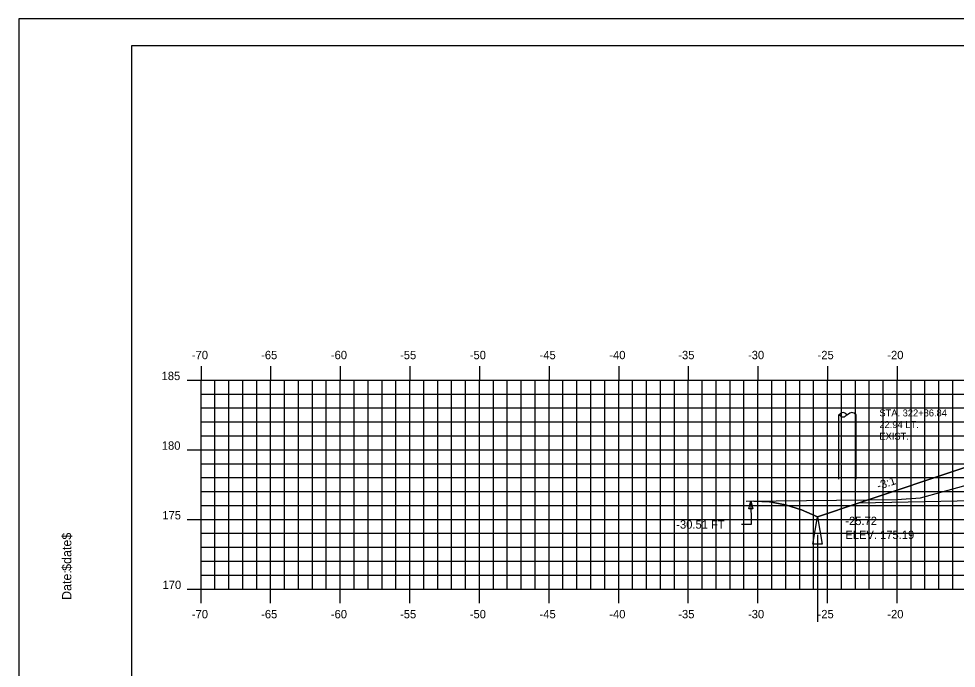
# Model space of a CAD drawing. Extents: x 1140094 to 1140264, y 608981 to 609091.
# Drawn here: x 1140093.6 to 1140161, y 609044.6 to 609091.3 of the extents above; entities that cross this region are included whole.
import ezdxf

# ---------------------------------------------------------------- set-up
doc = ezdxf.new("R2010")
doc.units = 0
for name, color, linetype in [('ANNOTATION', 7, 'Continuous'), ('BORDER', 7, 'Continuous'), ('D_Drainage_Ditch_Line', 7, 'Continuous'), ('D_Roadway_SlopeLines', 7, 'Continuous'), ('D_Roadway_SubGrade', 7, 'Continuous'), ('D_Text_Monospaced', 7, 'Continuous'), ('D_Text_Standard', 7, 'Continuous'), ('H_V ANNOTATION', 7, 'Continuous'), ('MAJOR', 7, 'Continuous'), ('MINOR', 7, 'Continuous'), ('PLOT BOUNDARY', 7, 'Continuous'), ('S_Roadway_Centerline', 7, 'Continuous'), ('S_Utilities_Pole_Power', 7, 'Continuous')]:
    doc.layers.add(name, color=color, linetype=linetype)

msp = doc.modelspace()

# ---------------------------------------------------------------- linework, layer by layer
msp.add_lwpolyline([(1140146.431, 609056.645), (1140147.575, 609056.586), (1140148.719, 609056.38), (1140149.863, 609056.028), (1140151.007, 609055.529), (1140154.007, 609056.529), (1140161.73, 609059.104), (1140161.731, 609059.104), (1140165.731, 609059.264), (1140176.731, 609059.484), (1140187.731, 609059.264), (1140191.731, 609059.104), (1140199.455, 609056.529), (1140202.455, 609055.529), (1140205.798, 609057.201), (1140207.048, 609057.751), (1140208.298, 609058.153), (1140209.548, 609058.405), (1140210.798, 609058.508)])
at = {"layer": 'BORDER'}
msp.add_lwpolyline([(1140101.732, 608984.335), (1140261.732, 608984.335), (1140261.732, 609089.335), (1140101.732, 609089.335)], close=True, dxfattribs=at)
at = {"layer": 'D_Drainage_Ditch_Line'}
msp.add_line((1140151.007, 609054.217), (1140151.006, 609047.974), dxfattribs=at)
msp.add_lwpolyline([(1140151.335, 609053.561), (1140150.679, 609053.561), (1140151.007, 609055.529)], close=True, dxfattribs=at)
at = {"layer": 'D_Roadway_SlopeLines'}
for points in [[(1140151.007, 609055.529), (1140149.863, 609056.028), (1140148.719, 609056.38), (1140147.575, 609056.586), (1140146.431, 609056.645)], [(1140154.007, 609056.529), (1140151.007, 609055.529)]]:
    msp.add_lwpolyline(points, dxfattribs=at)
at = {"layer": 'D_Roadway_SubGrade'}
msp.add_lwpolyline([(1140165.731, 609058.847), (1140165.731, 609059.014), (1140161.731, 609058.854), (1140161.731, 609059.104), (1140161.73, 609059.104), (1140154.007, 609056.529), (1140165.731, 609056.764)], close=True, dxfattribs=at)
at = {"layer": 'D_Text_Standard'}
msp.add_lwpolyline([(1140146.219, 609056.673), (1140146.241, 609054.971), (1140145.561, 609054.971)], dxfattribs=at)
msp.add_lwpolyline([(1140146.219, 609056.673), (1140146.372, 609056.093), (1140146.081, 609056.089)], close=True, dxfattribs=at)
at = {"layer": 'MAJOR'}
for p, q in [((1140106.731, 609066.337), (1140106.731, 609065.335)), ((1140111.731, 609066.337), (1140111.731, 609065.335)), ((1140116.731, 609066.337), (1140116.731, 609065.335)), ((1140121.731, 609066.337), (1140121.731, 609065.335)), ((1140126.731, 609066.337), (1140126.731, 609065.335)), ((1140131.731, 609066.337), (1140131.731, 609065.335)), ((1140136.731, 609066.337), (1140136.731, 609065.335)), ((1140141.731, 609066.337), (1140141.731, 609065.335)), ((1140146.731, 609066.337), (1140146.731, 609065.335)), ((1140151.731, 609066.337), (1140151.731, 609065.335)), ((1140156.731, 609066.337), (1140156.731, 609065.335)), ((1140105.729, 609065.335), (1140106.731, 609065.335)), ((1140106.731, 609065.335), (1140246.731, 609065.335)), ((1140106.731, 609050.335), (1140106.731, 609065.335)), ((1140106.731, 609050.335), (1140106.731, 609065.335)), ((1140106.731, 609065.335), (1140246.731, 609065.335)), ((1140111.731, 609050.335), (1140111.731, 609065.335)), ((1140116.731, 609050.335), (1140116.731, 609065.335)), ((1140121.731, 609050.335), (1140121.731, 609065.335)), ((1140126.731, 609050.335), (1140126.731, 609065.335)), ((1140131.731, 609050.335), (1140131.731, 609065.335)), ((1140136.731, 609050.335), (1140136.731, 609065.335)), ((1140141.731, 609050.335), (1140141.731, 609065.335)), ((1140146.731, 609050.335), (1140146.731, 609065.335)), ((1140151.731, 609050.335), (1140151.731, 609065.335)), ((1140156.731, 609050.335), (1140156.731, 609065.335)), ((1140105.729, 609060.335), (1140106.731, 609060.335)), ((1140106.731, 609060.335), (1140246.731, 609060.335)), ((1140105.729, 609055.335), (1140106.731, 609055.335)), ((1140106.731, 609055.335), (1140246.731, 609055.335)), ((1140105.729, 609050.335), (1140106.731, 609050.335)), ((1140106.731, 609050.335), (1140246.731, 609050.335)), ((1140106.731, 609050.335), (1140246.731, 609050.335)), ((1140106.731, 609049.333), (1140106.731, 609050.335)), ((1140111.731, 609049.333), (1140111.731, 609050.335)), ((1140116.731, 609049.333), (1140116.731, 609050.335)), ((1140121.731, 609049.333), (1140121.731, 609050.335)), ((1140126.731, 609049.333), (1140126.731, 609050.335)), ((1140131.731, 609049.333), (1140131.731, 609050.335)), ((1140136.731, 609049.333), (1140136.731, 609050.335)), ((1140141.731, 609049.333), (1140141.731, 609050.335)), ((1140146.731, 609049.333), (1140146.731, 609050.335)), ((1140151.731, 609049.333), (1140151.731, 609050.335)), ((1140156.731, 609049.333), (1140156.731, 609050.335))]:
    msp.add_line(p, q, dxfattribs=at)
at = {"layer": 'MINOR'}
for p, q in [((1140107.731, 609050.335), (1140107.731, 609065.335)), ((1140108.731, 609050.335), (1140108.731, 609065.335)), ((1140109.731, 609050.335), (1140109.731, 609065.335)), ((1140110.731, 609050.335), (1140110.731, 609065.335)), ((1140112.731, 609050.335), (1140112.731, 609065.335)), ((1140113.731, 609050.335), (1140113.731, 609065.335)), ((1140114.731, 609050.335), (1140114.731, 609065.335)), ((1140115.731, 609050.335), (1140115.731, 609065.335)), ((1140117.731, 609050.335), (1140117.731, 609065.335)), ((1140118.731, 609050.335), (1140118.731, 609065.335)), ((1140119.731, 609050.335), (1140119.731, 609065.335)), ((1140120.731, 609050.335), (1140120.731, 609065.335)), ((1140122.731, 609050.335), (1140122.731, 609065.335)), ((1140123.731, 609050.335), (1140123.731, 609065.335)), ((1140124.731, 609050.335), (1140124.731, 609065.335)), ((1140125.731, 609050.335), (1140125.731, 609065.335)), ((1140127.731, 609050.335), (1140127.731, 609065.335)), ((1140128.731, 609050.335), (1140128.731, 609065.335)), ((1140129.731, 609050.335), (1140129.731, 609065.335)), ((1140130.731, 609050.335), (1140130.731, 609065.335)), ((1140132.731, 609050.335), (1140132.731, 609065.335)), ((1140133.731, 609050.335), (1140133.731, 609065.335)), ((1140134.731, 609050.335), (1140134.731, 609065.335)), ((1140135.731, 609050.335), (1140135.731, 609065.335)), ((1140137.731, 609050.335), (1140137.731, 609065.335)), ((1140138.731, 609050.335), (1140138.731, 609065.335)), ((1140139.731, 609050.335), (1140139.731, 609065.335)), ((1140140.731, 609050.335), (1140140.731, 609065.335)), ((1140142.731, 609050.335), (1140142.731, 609065.335)), ((1140143.731, 609050.335), (1140143.731, 609065.335)), ((1140144.731, 609050.335), (1140144.731, 609065.335)), ((1140145.731, 609050.335), (1140145.731, 609065.335)), ((1140147.731, 609050.335), (1140147.731, 609065.335)), ((1140148.731, 609050.335), (1140148.731, 609065.335)), ((1140149.731, 609050.335), (1140149.731, 609065.335)), ((1140150.731, 609050.335), (1140150.731, 609065.335)), ((1140152.731, 609050.335), (1140152.731, 609065.335)), ((1140153.731, 609050.335), (1140153.731, 609065.335)), ((1140154.731, 609050.335), (1140154.731, 609065.335)), ((1140155.731, 609050.335), (1140155.731, 609065.335)), ((1140157.731, 609050.335), (1140157.731, 609065.335)), ((1140158.731, 609050.335), (1140158.731, 609065.335)), ((1140159.731, 609050.335), (1140159.731, 609065.335)), ((1140160.731, 609050.335), (1140160.731, 609065.335)), ((1140106.731, 609064.335), (1140246.731, 609064.335)), ((1140106.731, 609064.335), (1140107.733, 609064.335)), ((1140106.731, 609063.335), (1140246.731, 609063.335)), ((1140106.731, 609063.335), (1140107.733, 609063.335)), ((1140106.731, 609062.335), (1140246.731, 609062.335)), ((1140106.731, 609062.335), (1140107.733, 609062.335)), ((1140106.731, 609061.335), (1140246.731, 609061.335)), ((1140106.731, 609061.335), (1140107.733, 609061.335)), ((1140106.731, 609059.335), (1140246.731, 609059.335)), ((1140106.731, 609059.335), (1140107.733, 609059.335)), ((1140106.731, 609058.335), (1140246.731, 609058.335)), ((1140106.731, 609058.335), (1140107.733, 609058.335)), ((1140106.731, 609057.335), (1140246.731, 609057.335)), ((1140106.731, 609057.335), (1140107.733, 609057.335)), ((1140106.731, 609056.335), (1140246.731, 609056.335)), ((1140106.731, 609056.335), (1140107.733, 609056.335)), ((1140106.731, 609054.335), (1140246.731, 609054.335)), ((1140106.731, 609054.335), (1140107.733, 609054.335)), ((1140106.731, 609053.335), (1140246.731, 609053.335)), ((1140106.731, 609053.335), (1140107.733, 609053.335)), ((1140106.731, 609052.335), (1140246.731, 609052.335)), ((1140106.731, 609052.335), (1140107.733, 609052.335)), ((1140106.731, 609051.335), (1140246.731, 609051.335)), ((1140106.731, 609051.335), (1140107.733, 609051.335))]:
    msp.add_line(p, q, dxfattribs=at)
at = {"layer": 'PLOT BOUNDARY'}
msp.add_lwpolyline([(1140093.638, 608981.276), (1140263.638, 608981.276), (1140263.638, 609091.276), (1140093.638, 609091.276)], close=True, dxfattribs=at)
at = {"layer": 'S_Roadway_Centerline'}
msp.add_lwpolyline([(1140145.884, 609056.638), (1140156.704, 609056.772), (1140158.401, 609056.894), (1140164.633, 609058.607), (1140165.669, 609058.733), (1140165.972, 609058.746), (1140166.042, 609058.687), (1140166.187, 609058.687), (1140169.779, 609058.79), (1140177.071, 609059.28), (1140183.662, 609058.861), (1140188.271, 609058.728), (1140190.31, 609058.358), (1140191.022, 609058.194), (1140195.441, 609057.212), (1140195.554, 609057.192), (1140195.653, 609057.202), (1140199.545, 609058.254), (1140201.609, 609058.298), (1140221.444, 609058.751), (1140223.681, 609058.778), (1140246.731, 609058.72)], dxfattribs=at)
at = {"layer": 'S_Utilities_Pole_Power'}
for p, q in [((1140152.54, 609062.85), (1140152.696, 609062.96)), ((1140152.54, 609058.23), (1140152.543, 609062.85)), ((1140152.696, 609062.739), (1140152.54, 609062.85)), ((1140153.009, 609062.96), (1140153.165, 609062.85)), ((1140153.165, 609062.85), (1140153.009, 609062.739)), ((1140153.322, 609062.96), (1140153.165, 609062.85)), ((1140153.79, 609062.85), (1140153.634, 609062.96)), ((1140153.79, 609058.23), (1140153.793, 609062.85))]:
    msp.add_line(p, q, dxfattribs=at)
for centre, start, end in [((1140152.853, 609062.739), 90, 125.26439), ((1140152.853, 609062.96), 234.73561, 270), ((1140152.853, 609062.739), 54.73561, 90), ((1140152.853, 609062.96), 270, 305.26439), ((1140153.478, 609062.739), 90, 125.26439), ((1140153.478, 609062.739), 54.73561, 90)]:
    msp.add_arc(centre, 0.271, start, end, dxfattribs=at)

# ---------------------------------------------------------------- texts
at = {"layer": 'ANNOTATION'}
msp.add_text('-3:1', height=0.6, rotation=18.43482, dxfattribs=at).set_placement((1140155.386, 609057.443))
at = {"layer": 'BORDER'}
for s, p in [('$date$', (1140097.417, 609051.64)), ('Date:', (1140097.417, 609049.552))]:
    msp.add_text(s, height=0.6696, rotation=90, dxfattribs=at).set_placement(p)
at = {"layer": 'D_Text_Monospaced'}
for s, height, p in [('STA. 322+86.84', 0.49998, (1140155.457, 609062.728)), ('22.94 LT.', 0.5, (1140155.457, 609061.894)), ('EXIST. ', 0.5, (1140155.457, 609061.054))]:
    msp.add_text(s, height=height, dxfattribs=at).set_placement(p)
at = {"layer": 'D_Text_Standard'}
for s, p in [('-30.51 FT', (1140140.866, 609054.671)), ('-25.72', (1140153.007, 609054.929)), ('ELEV. 175.19', (1140153.007, 609053.927))]:
    msp.add_text(s, height=0.6, dxfattribs=at).set_placement(p)
at = {"layer": 'H_V ANNOTATION'}
for s, p in [('-70', (1140106.073, 609066.835)), ('-65', (1140111.049, 609066.835)), ('-60', (1140116.057, 609066.835)), ('-55', (1140121.028, 609066.835)), ('-50', (1140126.036, 609066.835)), ('-45', (1140131.049, 609066.835)), ('-40', (1140136.057, 609066.835)), ('-35', (1140141.012, 609066.835)), ('-30', (1140146.02, 609066.835)), ('-25', (1140151.017, 609066.835)), ('-20', (1140156.025, 609066.835)), ('185', (1140103.899, 609065.335)), ('180', (1140103.915, 609060.335)), ('175', (1140103.952, 609055.335)), ('170', (1140103.968, 609050.335)), ('-70', (1140106.073, 609048.235)), ('-65', (1140111.049, 609048.235)), ('-60', (1140116.057, 609048.235)), ('-55', (1140121.028, 609048.235)), ('-50', (1140126.036, 609048.235)), ('-45', (1140131.049, 609048.235)), ('-40', (1140136.057, 609048.235)), ('-35', (1140141.012, 609048.235)), ('-30', (1140146.02, 609048.235)), ('-25', (1140151.017, 609048.235)), ('-20', (1140156.025, 609048.235))]:
    msp.add_text(s, height=0.6, dxfattribs=at).set_placement(p)
at = {"layer": 'MAJOR'}
msp.add_text('-', height=0.006, dxfattribs=at).set_placement((1140106.727, 609050.335))

doc.saveas('drawing.dxf')
